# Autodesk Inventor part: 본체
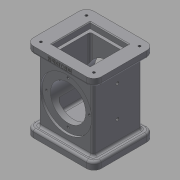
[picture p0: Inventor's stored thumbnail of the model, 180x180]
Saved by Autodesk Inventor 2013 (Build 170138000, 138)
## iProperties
Created: 2017-08
Part Number: 본체
Material: Generic
Document SubType Name: Modeling
Designer: Administrator
Density: 1 g/cm^3
Author: Administrator
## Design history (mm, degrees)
sketch "스케치2"
  geometry: L1 (-37, -54)-(37, -54); L2 (37, -54)-(37, 54); L3 (37, 54)-(-37, 54); L4 (-37, 54)-(-37, -54); L5 (-37, -54)-(37, 54); L6 (37, -54)-(-37, 54); 3 further points
  constraints: 12 end point, 3 midpoint, 2 parallel, 1 coincident, 1 horizontal, 1 perpendicular
  dimensions: "d0" = 74 distance of L2.end L3.end; "d2" = 108 distance of L3.end L1.start
extrude "돌출1" new body sketch "스케치2" stored distance "d3" = 66; taper "d4" = 0 deg
sketch "스케치3"
  geometry: L1 (74, -66)-(74, 0) reference; L2 (0, 0)-(74, 0) reference; L3 (0, -66)-(0, 0) reference; L4 (74, -66)-(0, -66) reference; L5 (-9, -74)-(83, -74); L6 (83, -74)-(83, 8); L7 (83, 8)-(-9, 8); L8 (-9, 8)-(-9, -74); L9 (-9, -74)-(83, 8); L10 (83, -74)-(-9, 8); 1 further point
  constraints: 12 end point, 2 midpoint, 2 parallel, 1 horizontal, 1 perpendicular
  dimensions: "d5" = 92 distance of L6.end L7.end; "d7" = 82 distance of L7.end L5.start
extrude "돌출2" join sketch "스케치3" distance "d8" = 10; taper "d9" = 0 deg
sketch "스케치4"
  geometry: L1 (74, -66)-(74, 0) reference; L2 (0, 0)-(74, 0) reference; L3 (0, 0)-(0, -66) reference; L4 (74, -66)-(0, -66) reference; L5 (74, 0)-(0, 0) reference; L6 (74, -66)-(74, 0) reference; L7 (0, -66)-(74, -66) reference; L8 (0, 0)-(0, -66) reference; L9 (-9, -74)-(83, -74) reference; L10 (83, -74)-(83, 8) reference; L11 (83, 8)-(-9, 8) reference; L12 (-9, 8)-(-9, -74) reference; L13 (-9, -74)-(83, -74); L14 (83, -74)-(83, 8); L15 (83, 8)-(-9, 8); L16 (-9, 8)-(-9, -74); L17 (-9, -74)-(83, 8); L18 (83, -74)-(-9, 8); 1 further point
  constraints: 12 end point, 2 midpoint, 2 parallel, 1 horizontal, 1 perpendicular
extrude "돌출3" join sketch "스케치4" distance "d10" = 10; taper "d11" = 0 deg
sketch "스케치5"
  geometry: L1 (22, -65)-(70, -65); L2 (70, -65)-(70, -17); L3 (70, -17)-(22, -17); L4 (22, -17)-(22, -65); L5 (22, -65)-(70, -17); L6 (70, -65)-(22, -17); 3 further points
  constraints: 12 end point, 3 midpoint, 2 parallel, 1 coincident, 1 horizontal, 1 perpendicular
  dimensions: "d12" = 48 distance of L2.end L3.end; "d14" = 48 distance of L3.end L1.start
extrude "돌출4" cut sketch "스케치5" distance "d15" = 16; taper "d16" = 0 deg
sketch "스케치6"
  geometry: C1 r 35 at (0, 0); 1 further point
  constraints: 1 centre point, 1 coincident
  dimensions: "d17" = 70 diameter of C1
extrude "돌출5" cut sketch "스케치6" distance "d19" = 3; taper "d20" = 0 deg
sketch "스케치7"
  geometry: C1 r 35 at (0, 0); 1 further point
  constraints: 1 centre point, 1 coincident
  dimensions: "d21" = 70 diameter of C1
extrude "돌출6" cut sketch "스케치7" distance "d23" = 3; taper "d24" = 0 deg
sketch "스케치8"
  geometry: C1 r 35 at (0, 0) reference; C2 r 24 at (0, 0)
  constraints: 1 centre point, 1 coincident
  dimensions: "d25" = 48 diameter of C2
extrude "돌출7" cut sketch "스케치8" stored distance "d27" = 3; taper "d28" = 0 deg
sketch "스케치9"
  geometry: L1 (20, 15)-(72, 15); L2 (72, 15)-(72, 67); L3 (72, 67)-(20, 67); L4 (20, 67)-(20, 15); L5 (20, 15)-(72, 67); L6 (72, 15)-(20, 67); 1 further point
  constraints: 12 end point, 2 midpoint, 2 parallel, 1 horizontal, 1 perpendicular
  dimensions: "d29" = 52 distance of L3.end L1.start; "d31" = 52 distance of L2.end L3.end
extrude "돌출8" cut sketch "스케치9" distance "d32" = 8; taper "d33" = 0 deg
sketch "스케치10"
  geometry: L1 (24, 19)-(68, 19); L2 (68, 19)-(68, 63); L3 (68, 63)-(24, 63); L4 (24, 63)-(24, 19); L5 (24, 19)-(68, 63); L6 (68, 19)-(24, 63); 1 further point
  constraints: 12 end point, 2 midpoint, 2 parallel, 1 horizontal, 1 perpendicular
  dimensions: "d34" = 44 distance of L2.end L3.end; "d36" = 44 distance of L3.end L1.start
extrude "돌출9" cut sketch "스케치10" distance "d37" = 74; taper "d38" = 0 deg
sketch "스케치11" dims "d39" = 58
  geometry: C1 r 24 at (0, 0) reference; C2 r 35 at (0, 0) reference; C3 r 2.847 at (0, 29); 1 further point
  constraints: 2 vertical alignment, 1 centre point, 1 coincident, 2 other
sketch "스케치12" dims "d41" = 58
  geometry: C1 r 24 at (0, 0) reference; C2 r 35 at (0, 0) reference; C3 r 3.611 at (0, -29); 1 further point
  constraints: 2 vertical alignment, 1 centre point, 1 coincident, 2 other
hole "구멍1" sketch "스케치11" diameter "d43" = 3.242; stored, may be unused: countersink angle "d47" = 90 deg, drill point angle "d49" = 118 deg; dims "d44" = 4, "d45" = 4, "d46" = 2, "d48" = 6
hole "구멍2" sketch "스케치12" diameter "d50" = 3.242; stored, may be unused: countersink angle "d54" = 90 deg, drill point angle "d56" = 118 deg; dims "d51" = 4, "d52" = 4, "d53" = 2, "d55" = 6
sketch "스케치13"
  geometry: C1 r 3.159 at (10, 10); 1 further point
  constraints: 1 centre point
  dimensions: "d60" = 36 horizontal distance of point (46, 41) C1.centre; "d61" = 31 vertical distance of C1.centre point (46, 41)
sketch "스케치14"
  geometry: C1 r 3.159 at (82, -72) reference; 1 further point
hole "구멍3" sketch "스케치14" at (82, -72) diameter "d62" = 3.242; stored, may be unused: countersink angle "d66" = 90 deg, drill point angle "d68" = 118 deg; dims "d63" = 4, "d64" = 4, "d65" = 2, "d67" = 6
hole "구멍4" sketch "스케치13" diameter "d69" = 3.242; stored, may be unused: countersink angle "d73" = 90 deg, drill point angle "d75" = 118 deg; dims "d70" = 4, "d71" = 4, "d72" = 2, "d74" = 6
fillet "모깎기1" dims "d88" = 10
fillet "모깎기2" dims "d89" = 3
fillet "모깎기3" dims "d90" = 3
fillet "모깎기4" dims "d91" = 3
fillet "모깎기5" dims "d92" = 3
fillet "모깎기6" dims "d93" = 3
fillet "모깎기7" dims "d94" = 3
sketch "스케치15"
  geometry: L1 (95, 61)-(95, -1) reference; C1 r 7.226 at (57, 30); C2 r 13.45 at (15, 30); 1 further point
  constraints: 2 centre point, 2 horizontal alignment
  dimensions: "d95" = 38 distance from line of C1.centre L1; "d96" = 42 distance of C2.centre C1.centre
hole "구멍5" sketch "스케치15" at (15, 30), (57, 30) diameter "d97" = 4.134; stored, may be unused: countersink angle "d101" = 90 deg, drill point angle "d103" = 118 deg; dims "d98" = 4, "d99" = 4, "d100" = 2, "d102" = 19.75
chamfer "모따기1" distance "d104" = 1; stored, may be unused: second distance "d105" = 2, angle "d106" = 45 deg
fillet "모깎기8" dims "d107" = 3
sketch "스케치17"
  geometry: L1 (0, 0)-(72, 0) reference; L2 (8.67, -1.598)-(63.33, -1.598); L3 (63.33, -1.598)-(63.33, -6.402); L4 (63.33, -6.402)-(8.67, -6.402); L5 (8.67, -6.402)-(8.67, -1.598); L6 (8.67, -4)-(63.33, -4); L7 (36, -1.598)-(36, -6.402); L8 (-10, 0)-(-10, -7) reference; 1 further point
  constraints: 4 end point, 4 midpoint, 2 other
  dimensions: "d110" = 4 distance between parallel lines of L1 L6; "d111" = 46 distance between parallel lines of L8 L7
extrude "돌출10" join sketch "스케치17" distance "d112" = 0.5; taper "d113" = 0 deg
node "솔리드1"
pattern_circular "원형 패턴1" dims angle "d58" = 360 deg
pattern_linear "직사각형 패턴1" dims "d78" = 72, "d81" = 62
pattern_linear "직사각형 패턴2" dims "d84" = 72, "d87" = 62
node "투영된 루프1"
